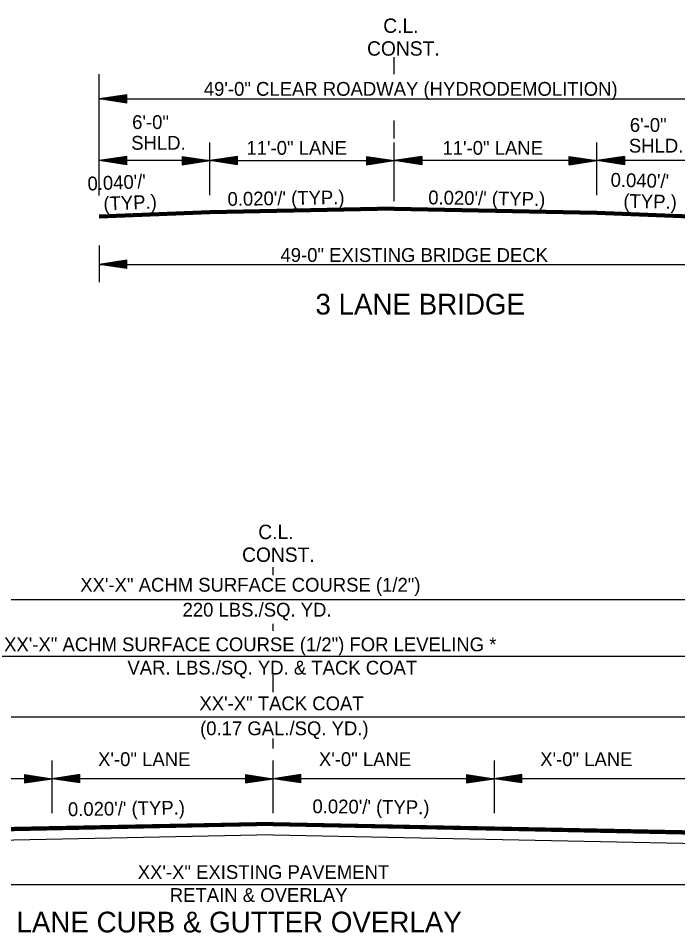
# Model space of a CAD drawing. Extents: x 544199 to 1930787, y -1968972 to 596640.
# Drawn here: x 551829.5 to 552187.2, y -1963317.3 to -1962821 of the extents above; entities that cross this region are included whole.
import ezdxf

# ---------------------------------------------------------------- set-up
doc = ezdxf.new("R2010")
doc.units = 0
doc.layers.add('R_Border', color=7, linetype='Continuous')
doc.layers.add('R_Draft', color=7, linetype='Continuous')

msp = doc.modelspace()

# ---------------------------------------------------------------- linework, layer by layer
at = {"layer": 'R_Border'}
for p, q in [((551933.33, -1962925.51), (551873.33, -1962927.91)), ((551933.33, -1962925.81), (551873.33, -1962928.21)), ((551933.33, -1962926.11), (551873.33, -1962928.51)), ((551933.33, -1962926.41), (551873.33, -1962928.81)), ((551933.33, -1962926.71), (551873.33, -1962929.11)), ((551933.33, -1962927.01), (551873.33, -1962929.41)), ((551933.33, -1962927.18), (551873.33, -1962929.58)), ((552143.33, -1962925.71), (552203.33, -1962928.11)), ((552143.33, -1962926.01), (552203.33, -1962928.41)), ((552143.33, -1962926.31), (552203.33, -1962928.71)), ((552143.33, -1962926.61), (552203.33, -1962929.01)), ((552143.33, -1962926.91), (552203.33, -1962929.31)), ((552143.33, -1962927.21), (552203.33, -1962929.61)), ((552143.33, -1962927.38), (552203.33, -1962929.78))]:
    msp.add_line(p, q, dxfattribs=at)
at = {"layer": 'R_Draft'}
for p, q in [((552033.33, -1962851.35), (552033.33, -1962842.05)), ((551873.33, -1962917.13), (551873.33, -1962851.4)), ((551888.33, -1962862.52), (551873.33, -1962864.77)), ((551888.33, -1962862.89), (551875.83, -1962864.77)), ((551888.33, -1962863.27), (551878.41, -1962864.77)), ((551888.33, -1962867.02), (551888.33, -1962862.52)), ((551873.33, -1962864.77), (552203.33, -1962864.77)), ((551888.33, -1962867.02), (551873.33, -1962864.77)), ((551888.33, -1962866.64), (551875.83, -1962864.77)), ((551888.33, -1962866.26), (551878.41, -1962864.77)), ((551888.33, -1962863.65), (551880.91, -1962864.77)), ((551888.33, -1962865.88), (551880.91, -1962864.77)), ((551888.33, -1962864.03), (551883.45, -1962864.77)), ((551888.33, -1962865.49), (551883.45, -1962864.77)), ((551888.33, -1962864.41), (551885.96, -1962864.77)), ((551888.33, -1962865.12), (551885.96, -1962864.77)), ((552033.33, -1962886.29), (552033.33, -1962876.42)), ((551933.33, -1962916.96), (551933.33, -1962888.41)), ((552033.33, -1962910.07), (552033.33, -1962888.41)), ((552033.33, -1962910.73), (552033.33, -1962888.41)), ((552143.33, -1962916.96), (552143.33, -1962888.41)), ((551888.33, -1962896.05), (551873.33, -1962898.3)), ((551888.33, -1962896.43), (551875.83, -1962898.3)), ((551888.33, -1962896.81), (551878.41, -1962898.3)), ((551888.33, -1962897.19), (551880.91, -1962898.3)), ((551888.33, -1962897.57), (551883.45, -1962898.3)), ((551888.33, -1962897.95), (551885.96, -1962898.3)), ((551888.33, -1962900.55), (551888.33, -1962896.05)), ((551918.33, -1962896.05), (551933.33, -1962898.3)), ((551918.33, -1962896.05), (551918.33, -1962900.55)), ((551918.33, -1962896.43), (551930.82, -1962898.3)), ((551918.33, -1962896.81), (551928.24, -1962898.3)), ((551918.33, -1962897.19), (551925.75, -1962898.3)), ((551918.33, -1962897.58), (551923.2, -1962898.3)), ((551918.33, -1962897.95), (551920.7, -1962898.3)), ((551948.33, -1962896.05), (551933.33, -1962898.3)), ((551948.33, -1962896.43), (551935.83, -1962898.3)), ((551948.33, -1962896.81), (551938.41, -1962898.3)), ((551948.33, -1962897.19), (551940.91, -1962898.3)), ((551948.33, -1962897.57), (551943.45, -1962898.3)), ((551948.33, -1962897.95), (551945.96, -1962898.3)), ((551948.33, -1962900.55), (551948.33, -1962896.05)), ((552018.33, -1962896.05), (552033.33, -1962898.3)), ((552018.33, -1962896.05), (552018.33, -1962900.55)), ((552018.33, -1962896.43), (552030.82, -1962898.3)), ((552018.33, -1962896.81), (552028.24, -1962898.3)), ((552018.33, -1962897.19), (552025.75, -1962898.3)), ((552018.33, -1962897.58), (552023.2, -1962898.3)), ((552018.33, -1962897.95), (552020.7, -1962898.3)), ((552048.33, -1962896.05), (552033.33, -1962898.3)), ((552048.33, -1962896.43), (552035.83, -1962898.3)), ((552048.33, -1962896.81), (552038.41, -1962898.3)), ((552048.33, -1962897.19), (552040.91, -1962898.3)), ((552048.33, -1962897.58), (552043.45, -1962898.3)), ((552048.33, -1962897.95), (552045.96, -1962898.3)), ((552048.33, -1962896.05), (552048.33, -1962900.55)), ((552128.33, -1962896.05), (552143.33, -1962898.3)), ((552128.33, -1962900.55), (552128.33, -1962896.05)), ((552128.33, -1962896.43), (552140.82, -1962898.3)), ((552128.33, -1962896.81), (552138.24, -1962898.3)), ((552128.33, -1962897.19), (552135.75, -1962898.3)), ((552128.33, -1962897.57), (552133.2, -1962898.3)), ((552128.33, -1962897.95), (552130.7, -1962898.3)), ((552158.33, -1962896.05), (552143.33, -1962898.3)), ((552158.33, -1962896.43), (552145.83, -1962898.3)), ((552158.33, -1962896.81), (552148.41, -1962898.3)), ((552158.33, -1962897.19), (552150.91, -1962898.3)), ((552158.33, -1962897.58), (552153.45, -1962898.3)), ((552158.33, -1962897.95), (552155.96, -1962898.3)), ((552158.33, -1962896.05), (552158.33, -1962900.55)), ((551933.33, -1962898.3), (551873.33, -1962898.3)), ((551888.33, -1962900.55), (551873.33, -1962898.3)), ((551888.33, -1962900.18), (551875.83, -1962898.3)), ((551888.33, -1962899.8), (551878.41, -1962898.3)), ((551888.33, -1962899.42), (551880.91, -1962898.3)), ((551888.33, -1962899.03), (551883.45, -1962898.3)), ((551888.33, -1962898.66), (551885.96, -1962898.3)), ((551918.33, -1962900.55), (551933.33, -1962898.3)), ((551918.33, -1962899.04), (551923.2, -1962898.3)), ((551918.33, -1962899.8), (551928.24, -1962898.3)), ((551918.33, -1962900.18), (551930.82, -1962898.3)), ((551918.33, -1962899.42), (551925.75, -1962898.3)), ((551918.33, -1962898.66), (551920.7, -1962898.3)), ((551933.33, -1962898.3), (552043.33, -1962898.3)), ((551948.33, -1962900.55), (551933.33, -1962898.3)), ((551948.33, -1962900.18), (551935.83, -1962898.3)), ((551948.33, -1962899.8), (551938.41, -1962898.3)), ((551948.33, -1962899.42), (551940.91, -1962898.3)), ((551948.33, -1962899.03), (551943.45, -1962898.3)), ((551948.33, -1962898.66), (551945.96, -1962898.3)), ((552018.33, -1962900.55), (552033.33, -1962898.3)), ((552018.33, -1962899.04), (552023.2, -1962898.3)), ((552018.33, -1962899.8), (552028.24, -1962898.3)), ((552018.33, -1962900.18), (552030.82, -1962898.3)), ((552018.33, -1962899.42), (552025.75, -1962898.3)), ((552018.33, -1962898.66), (552020.7, -1962898.3)), ((552048.33, -1962900.55), (552033.33, -1962898.3)), ((552033.33, -1962920.36), (552033.33, -1962901.42)), ((552048.33, -1962900.18), (552035.83, -1962898.3)), ((552048.33, -1962899.8), (552038.41, -1962898.3)), ((552048.33, -1962899.42), (552040.91, -1962898.3)), ((552143.33, -1962898.3), (552043.33, -1962898.3)), ((552048.33, -1962899.04), (552043.45, -1962898.3)), ((552048.33, -1962898.66), (552045.96, -1962898.3)), ((552128.33, -1962900.55), (552143.33, -1962898.3)), ((552128.33, -1962899.03), (552133.2, -1962898.3)), ((552128.33, -1962899.8), (552138.24, -1962898.3)), ((552128.33, -1962900.18), (552140.82, -1962898.3)), ((552128.33, -1962899.42), (552135.75, -1962898.3)), ((552128.33, -1962898.66), (552130.7, -1962898.3)), ((552203.33, -1962898.3), (552143.33, -1962898.3)), ((552158.33, -1962900.55), (552143.33, -1962898.3)), ((552158.33, -1962900.18), (552145.83, -1962898.3)), ((552158.33, -1962899.8), (552148.41, -1962898.3)), ((552158.33, -1962899.42), (552150.91, -1962898.3)), ((552158.33, -1962899.04), (552153.45, -1962898.3)), ((552158.33, -1962898.66), (552155.96, -1962898.3)), ((552033.33, -1962923.51), (551933.33, -1962925.51)), ((552033.33, -1962923.81), (551933.33, -1962925.81)), ((552033.33, -1962924.11), (551933.33, -1962926.11)), ((552033.33, -1962924.41), (551933.33, -1962926.41)), ((552033.33, -1962924.71), (551933.33, -1962926.71)), ((552033.33, -1962925.01), (551933.33, -1962927.01)), ((552033.33, -1962925.18), (551933.33, -1962927.18)), ((552033.33, -1962923.51), (552143.33, -1962925.71)), ((552033.33, -1962923.81), (552143.33, -1962926.01)), ((552033.33, -1962924.11), (552143.33, -1962926.31)), ((552033.33, -1962924.41), (552143.33, -1962926.61)), ((552033.33, -1962924.71), (552143.33, -1962926.91)), ((552033.33, -1962925.01), (552143.33, -1962927.21)), ((552033.33, -1962925.18), (552143.33, -1962927.38)), ((551873.33, -1962944.32), (551873.33, -1962964.32)), ((551888.32, -1962952.32), (551873.32, -1962954.57)), ((551888.32, -1962956.82), (551888.32, -1962952.32)), ((551888.32, -1962956.82), (551873.32, -1962954.57)), ((551873.33, -1962954.58), (552203.33, -1962954.63)), ((551888.32, -1962952.69), (551875.82, -1962954.57)), ((551888.32, -1962956.44), (551875.82, -1962954.57)), ((551888.32, -1962953.08), (551878.4, -1962954.57)), ((551888.32, -1962956.06), (551878.4, -1962954.57)), ((551888.32, -1962953.45), (551880.9, -1962954.57)), ((551888.32, -1962955.69), (551880.9, -1962954.57)), ((551888.32, -1962953.83), (551883.44, -1962954.57)), ((551888.32, -1962955.3), (551883.44, -1962954.57)), ((551888.32, -1962954.22), (551885.95, -1962954.57)), ((551888.32, -1962954.92), (551885.95, -1962954.57)), ((551967.78, -1963123.28), (551967.78, -1963118.87)), ((551719.95, -1963136.38), (552215.61, -1963136.38)), ((551967.78, -1963153.41), (551967.78, -1963149.74)), ((551719.95, -1963167.25), (552215.61, -1963167.25)), ((551967.78, -1963186.77), (551967.78, -1963177.47)), ((551719.95, -1963200.18), (552215.61, -1963200.18)), ((551967.78, -1963217.31), (551967.78, -1963211.84)), ((551847.85, -1963252.38), (551847.85, -1963223.83)), ((551967.78, -1963233.72), (551967.78, -1963223.83)), ((551967.78, -1963252.38), (551967.78, -1963223.83)), ((552087.78, -1963252.38), (552087.78, -1963223.83)), ((551847.85, -1963233.72), (551727.85, -1963233.72)), ((551832.85, -1963231.47), (551847.85, -1963233.72)), ((551832.85, -1963231.47), (551832.85, -1963235.97)), ((551832.85, -1963231.85), (551845.34, -1963233.72)), ((551832.85, -1963232.23), (551842.76, -1963233.72)), ((551832.85, -1963232.6), (551840.27, -1963233.72)), ((551832.85, -1963232.99), (551837.72, -1963233.72)), ((551832.85, -1963233.37), (551835.22, -1963233.72)), ((551832.85, -1963235.97), (551847.85, -1963233.72)), ((551832.85, -1963234.46), (551837.72, -1963233.72)), ((551832.85, -1963235.21), (551842.76, -1963233.72)), ((551832.85, -1963235.6), (551845.34, -1963233.72)), ((551832.85, -1963234.84), (551840.27, -1963233.72)), ((551832.85, -1963234.07), (551835.22, -1963233.72)), ((551862.85, -1963231.47), (551847.85, -1963233.72)), ((551967.78, -1963233.72), (551847.85, -1963233.72)), ((551862.85, -1963235.97), (551847.85, -1963233.72)), ((551862.85, -1963231.85), (551850.35, -1963233.72)), ((551862.85, -1963235.6), (551850.35, -1963233.72)), ((551862.85, -1963232.23), (551852.93, -1963233.72)), ((551862.85, -1963235.21), (551852.93, -1963233.72)), ((551862.85, -1963232.6), (551855.43, -1963233.72)), ((551862.85, -1963234.84), (551855.43, -1963233.72)), ((551862.85, -1963232.99), (551857.97, -1963233.72)), ((551862.85, -1963234.45), (551857.97, -1963233.72)), ((551862.85, -1963233.37), (551860.48, -1963233.72)), ((551862.85, -1963234.07), (551860.48, -1963233.72)), ((551862.85, -1963235.97), (551862.85, -1963231.47)), ((551952.78, -1963231.47), (551967.78, -1963233.72)), ((551952.78, -1963231.47), (551952.78, -1963235.97)), ((551952.78, -1963231.85), (551965.27, -1963233.72)), ((551952.78, -1963232.23), (551962.69, -1963233.72)), ((551952.78, -1963232.6), (551960.19, -1963233.72)), ((551952.78, -1963232.99), (551957.65, -1963233.72)), ((551952.78, -1963233.37), (551955.15, -1963233.72)), ((551952.78, -1963235.97), (551967.78, -1963233.72)), ((551952.78, -1963234.46), (551957.65, -1963233.72)), ((551952.78, -1963235.21), (551962.69, -1963233.72)), ((551952.78, -1963235.6), (551965.27, -1963233.72)), ((551952.78, -1963234.84), (551960.19, -1963233.72)), ((551952.78, -1963234.07), (551955.15, -1963233.72)), ((551982.78, -1963231.47), (551967.78, -1963233.72)), ((551967.78, -1963252.38), (551967.78, -1963233.72)), ((552087.7, -1963233.72), (551967.78, -1963233.72)), ((551982.78, -1963235.97), (551967.78, -1963233.72)), ((551982.78, -1963231.85), (551970.28, -1963233.72)), ((551982.78, -1963235.6), (551970.28, -1963233.72)), ((551982.78, -1963232.23), (551972.86, -1963233.72)), ((551982.78, -1963235.21), (551972.86, -1963233.72)), ((551982.78, -1963232.6), (551975.36, -1963233.72)), ((551982.78, -1963234.84), (551975.36, -1963233.72)), ((551982.78, -1963232.99), (551977.9, -1963233.72)), ((551982.78, -1963234.45), (551977.9, -1963233.72)), ((551982.78, -1963233.37), (551980.41, -1963233.72)), ((551982.78, -1963234.07), (551980.41, -1963233.72)), ((551982.78, -1963235.97), (551982.78, -1963231.47)), ((552072.7, -1963231.47), (552087.7, -1963233.72)), ((552072.7, -1963231.47), (552072.7, -1963235.97)), ((552072.7, -1963231.85), (552085.2, -1963233.72)), ((552072.7, -1963232.23), (552082.62, -1963233.72)), ((552072.7, -1963232.6), (552080.12, -1963233.72)), ((552072.7, -1963232.99), (552077.58, -1963233.72)), ((552072.7, -1963233.37), (552075.07, -1963233.72)), ((552072.7, -1963235.97), (552087.7, -1963233.72)), ((552072.7, -1963234.46), (552077.58, -1963233.72)), ((552072.7, -1963235.21), (552082.62, -1963233.72)), ((552072.7, -1963235.6), (552085.2, -1963233.72)), ((552072.7, -1963234.84), (552080.12, -1963233.72)), ((552072.7, -1963234.07), (552075.07, -1963233.72)), ((552102.7, -1963231.47), (552087.7, -1963233.72)), ((552207.63, -1963233.72), (552087.7, -1963233.72)), ((552102.7, -1963235.97), (552087.7, -1963233.72)), ((552102.7, -1963231.85), (552090.21, -1963233.72)), ((552102.7, -1963235.6), (552090.21, -1963233.72)), ((552102.7, -1963232.23), (552092.79, -1963233.72)), ((552102.7, -1963235.21), (552092.79, -1963233.72)), ((552102.7, -1963232.6), (552095.29, -1963233.72)), ((552102.7, -1963234.84), (552095.29, -1963233.72)), ((552102.7, -1963232.99), (552097.83, -1963233.72)), ((552102.7, -1963234.45), (552097.83, -1963233.72)), ((552102.7, -1963233.37), (552100.33, -1963233.72)), ((552102.7, -1963234.07), (552100.33, -1963233.72)), ((552102.7, -1963235.97), (552102.7, -1963231.47)), ((551967.78, -1963257.43), (551719.95, -1963262.38)), ((551967.78, -1963257.73), (551720.14, -1963262.68)), ((551967.78, -1963258.03), (551720.33, -1963262.97)), ((551967.78, -1963258.33), (551720.51, -1963263.27)), ((551967.78, -1963258.63), (551720.7, -1963263.57)), ((551967.78, -1963258.93), (551720.89, -1963263.86)), ((551967.78, -1963259.13), (551727.85, -1963263.92)), ((551967.78, -1963257.43), (552215.61, -1963262.38)), ((551967.78, -1963257.73), (552215.43, -1963262.68)), ((551967.78, -1963258.03), (552215.24, -1963262.97)), ((551967.78, -1963258.33), (552215.05, -1963263.27)), ((551967.78, -1963258.63), (552214.87, -1963263.57)), ((551967.78, -1963258.93), (552214.68, -1963263.86)), ((551967.78, -1963259.13), (552207.63, -1963263.92)), ((551967.85, -1963264.22), (551727.85, -1963269.02)), ((551967.85, -1963264.22), (552207.63, -1963269.02)), ((551727.85, -1963291.19), (552207.63, -1963291.19))]:
    msp.add_line(p, q, dxfattribs=at)

# ---------------------------------------------------------------- texts
for s, height, p in [('C.L.', 7.8, (552027.48, -1962828.95)), ('CONST.', 7.8, (552018.7, -1962841.32)), ('49\'-0" CLEAR ROADWAY (HYDRODEMOLITION)', 7.5, (551930.14, -1962863.1)), ('6\'-0" ', 7.5, (551891.26, -1962881.13)), ('6\'-0" ', 7.5, (552161.25, -1962882.67)), ('SHLD.', 7.5, (551890.75, -1962892.38)), ('11\'-0" LANE', 7.5, (551953.27, -1962895.13)), ('11\'-0" LANE', 7.5, (552059.61, -1962895.13)), ('SHLD.', 7.5, (552160.75, -1962893.92)), ('49-0" EXISTING BRIDGE DECK', 7.5, (551971.72, -1962953.25)), ('3 LANE BRIDGE', 11.25, (551990.7, -1962981.81)), ('C.L.', 7.8, (551959.67, -1963103.67)), ('CONST.', 7.8, (551950.89, -1963116.04)), ('XX\'-X" ACHM SURFACE COURSE (1/2")', 7.5, (551863.12, -1963132.22)), ('220 LBS./SQ. YD. ', 7.5, (551918.6, -1963145.76)), ('XX\'-X" ACHM SURFACE COURSE (1/2") FOR LEVELING *', 7.5, (551821.8, -1963164.57)), ('VAR. LBS./SQ. YD. & TACK COAT', 7.5, (551888.7, -1963177.19)), ('XX\'-X" TACK COAT', 7.5, (551927.76, -1963196.58)), ('(0.17 GAL./SQ. YD.)', 7.5, (551928.12, -1963210.12)), ('X\'-0" LANE', 7.5, (551872.78, -1963226.86)), ('X\'-0" LANE', 7.5, (551992.59, -1963226.86)), ('X\'-0" LANE', 7.5, (552112.64, -1963226.86)), ('XX\'-X" EXISTING PAVEMENT', 7.5, (551894.29, -1963288.14)), ('RETAIN & OVERLAY', 7.5, (551911.7, -1963300.61)), ('4 LANE CURB & GUTTER OVERLAY', 11.25, (551815.96, -1963317.13))]:
    msp.add_text(s, height=height, dxfattribs=at).set_placement(p)
for s, rotation, p in [("  0.040'/'", 2.448, (551861.62, -1962914.79)), ("0.040'/' ", 358.6816, (552150.76, -1962912.43)), (' (TYP.)', 2.448, (551873.05, -1962925.56)), ("0.020'/' (TYP.)", 0.8719, (551943.06, -1962922.88)), ("0.020'/' (TYP.)", 359.1281, (552051.85, -1962921.99)), ('(TYP.)', 358.6816, (552157.7, -1962923.84)), ("0.020'/' (TYP.)", 0.8518, (551856.49, -1963254.07)), ("0.020'/' (TYP.)", 359.4444, (551989.05, -1963252.41))]:
    msp.add_text(s, height=7.5, rotation=rotation, dxfattribs=at).set_placement(p)

doc.saveas('drawing.dxf')
